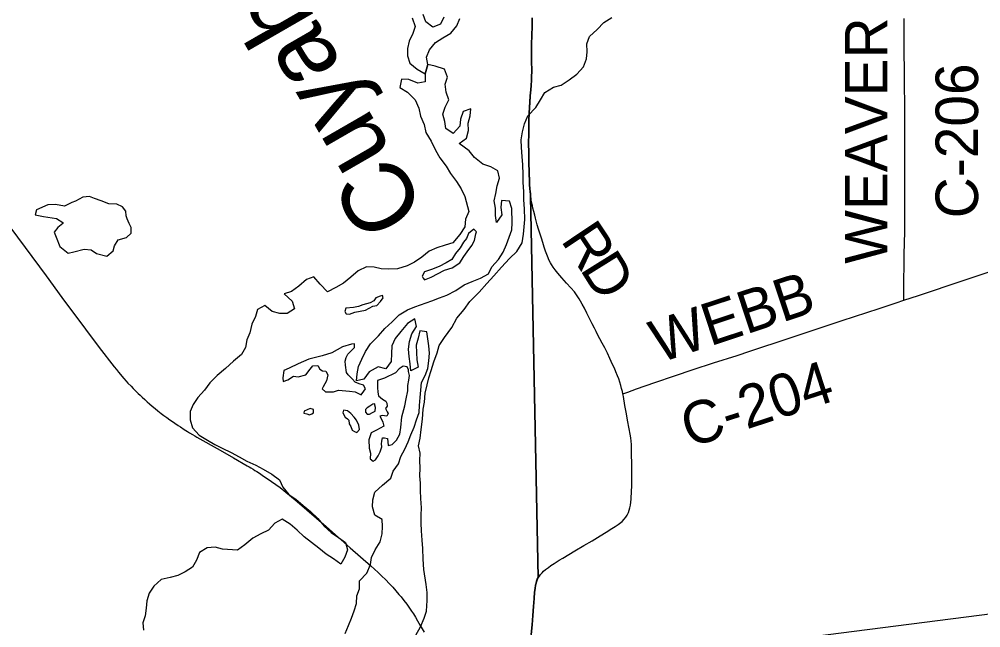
# Model space of a CAD drawing. Extents: x 0 to 34, y 0 to 22.
# Drawn here: x 4.358 to 5.643, y 17.616 to 18.429 of the extents above; entities that cross this region are included whole.
import ezdxf

# ---------------------------------------------------------------- set-up
doc = ezdxf.new("R2010")
doc.units = 0
for name, color, linetype in [('GM_X_Corporation', 7, 'Continuous'), ('GM_X_County_Road', 7, 'Continuous'), ('GM_X_County_Road_Text', 7, 'Continuous'), ('GM_X_Major_Lake', 7, 'Continuous'), ('GM_X_Major_River', 7, 'Continuous'), ('GM_X_Major_River_Text', 7, 'Continuous'), ('GM_X_Minor_Lake', 7, 'Continuous'), ('GM_X_Minor_River', 7, 'Continuous'), ('GM_X_State_Route', 7, 'Continuous'), ('GM_X_Township_Road', 7, 'Continuous'), ('GM_X_Township_Road_Text', 7, 'Continuous'), ('SH_Text', 7, 'Continuous')]:
    doc.layers.add(name, color=color, linetype=linetype)

msp = doc.modelspace()

# ---------------------------------------------------------------- linework, layer by layer
at = {"layer": 'GM_X_Corporation'}
for points in [[(5.0422, 17.6065), (5.0432, 17.6198), (5.0441, 17.6321), (5.0451, 17.6441), (5.046, 17.6549), (5.0467, 17.6631), (5.0472, 17.6682), (5.0479, 17.6725), (5.0486, 17.6754), (5.0493, 17.6779), (5.0502, 17.6805), (5.0513, 17.683), (5.0413, 18.1922), (5.041, 18.1954), (5.0406, 18.1989), (5.0404, 18.2021), (5.04, 18.208), (5.0398, 18.2139), (5.0394, 18.2224), (5.0392, 18.2271), (5.0391, 18.2349), (5.0389, 18.2412), (5.0388, 18.2477), (5.0388, 18.2536), (5.0387, 18.2601), (5.0387, 18.2653), (5.0388, 18.2734), (5.0388, 18.2852), (5.039, 18.2939), (5.0394, 18.3029), (5.0399, 18.3112), (5.0404, 18.3184), (5.0409, 18.3266), (5.0416, 18.3344), (5.042, 18.3404), (5.0424, 18.3475), (5.0427, 18.3534), (5.0428, 18.3582), (5.0428, 18.364), (5.0427, 18.3692), (5.0425, 18.3748), (5.0424, 18.3787), (5.0424, 18.3848), (5.0424, 18.3885), (5.0425, 18.3967), (5.0429, 18.4064), (5.0433, 18.4204), (5.0435, 18.4306)], [(5.0422, 17.6065), (5.0432, 17.6198), (5.0441, 17.6321), (5.0451, 17.6441), (5.046, 17.6549), (5.0467, 17.6631), (5.0472, 17.6682), (5.0479, 17.6725), (5.0486, 17.6754), (5.0493, 17.6779), (5.0502, 17.6805), (5.0513, 17.683), (5.0413, 18.1922), (5.041, 18.1954), (5.0406, 18.1989), (5.0404, 18.2021), (5.04, 18.208), (5.0398, 18.2139), (5.0394, 18.2224), (5.0392, 18.2271), (5.0391, 18.2349), (5.0389, 18.2412), (5.0388, 18.2477), (5.0388, 18.2536), (5.0387, 18.2601), (5.0387, 18.2653), (5.0388, 18.2734), (5.0388, 18.2852), (5.039, 18.2939), (5.0394, 18.3029), (5.0399, 18.3112), (5.0404, 18.3184), (5.0409, 18.3266), (5.0416, 18.3344), (5.042, 18.3404), (5.0424, 18.3475), (5.0427, 18.3534), (5.0428, 18.3582), (5.0428, 18.364), (5.0427, 18.3692), (5.0425, 18.3748), (5.0424, 18.3787), (5.0424, 18.3848), (5.0424, 18.3885), (5.0425, 18.3967), (5.0429, 18.4064), (5.0433, 18.4204), (5.0435, 18.4306)], [(5.0435, 18.4306), (5.0433, 18.4204), (5.0429, 18.4064), (5.0425, 18.3967), (5.0424, 18.3885), (5.0424, 18.3848), (5.0424, 18.3787), (5.0425, 18.3748), (5.0427, 18.3692), (5.0428, 18.364), (5.0428, 18.3582), (5.0427, 18.3534), (5.0424, 18.3475), (5.042, 18.3404), (5.0416, 18.3344), (5.0409, 18.3266), (5.0404, 18.3184), (5.0399, 18.3112), (5.0394, 18.3029), (5.039, 18.2939), (5.0388, 18.2852), (5.0388, 18.2734), (5.0387, 18.2653), (5.0387, 18.2601), (5.0388, 18.2536), (5.0388, 18.2477), (5.0389, 18.2412), (5.0391, 18.2349), (5.0392, 18.2271), (5.0394, 18.2224), (5.0398, 18.2139), (5.04, 18.208), (5.0404, 18.2021), (5.0406, 18.1989), (5.041, 18.1954), (5.0413, 18.1922), (5.0513, 17.683), (5.0502, 17.6805), (5.0493, 17.6779), (5.0486, 17.6754), (5.0479, 17.6725), (5.0472, 17.6682), (5.0467, 17.6631), (5.046, 17.6549), (5.0451, 17.6441), (5.0441, 17.6321), (5.0432, 17.6198), (5.0422, 17.6065)]]:
    msp.add_lwpolyline(points, dxfattribs=at)
at = {"layer": 'GM_X_County_Road'}
for points in [[(5.5403, 18.0535), (5.5404, 18.0653), (5.5408, 18.1144), (5.5414, 18.1454), (5.5415, 18.169), (5.5416, 18.2026), (5.5417, 18.2162), (5.5417, 18.2591), (5.5418, 18.2852), (5.5416, 18.307), (5.5413, 18.3486), (5.5412, 18.3586), (5.5408, 18.3865), (5.5406, 18.402), (5.5406, 18.4299)], [(5.5403, 18.0535), (5.5599, 18.0598), (5.6195, 18.0797), (5.653, 18.0911)], [(5.1646, 17.9281), (5.1711, 17.9306), (5.1831, 17.9351), (5.2075, 17.9434), (5.2337, 17.9522), (5.2588, 17.9607), (5.286, 17.9695), (5.3174, 17.9796), (5.3344, 17.9855), (5.387, 18.0026), (5.4123, 18.0112), (5.4578, 18.0263), (5.5075, 18.0423), (5.5298, 18.0501), (5.5403, 18.0535)]]:
    msp.add_lwpolyline(points, dxfattribs=at)
at = {"layer": 'GM_X_Major_Lake'}
for p, q in [((4.9041, 18.3683), (4.9002, 18.356)), ((4.9041, 18.3683), (4.9002, 18.356)), ((4.9473, 18.1235), (4.941, 18.1159)), ((4.8269, 18.0501), (4.817, 18.0474)), ((4.8609, 17.9563), (4.8462, 17.9494)), ((4.7846, 17.933), (4.799, 17.9319)), ((4.8264, 17.9117), (4.823, 17.9097)), ((4.7459, 17.9004), (4.7489, 17.9016)), ((4.7982, 17.8929), (4.7986, 17.8883))]:
    msp.add_line(p, q, dxfattribs=at)
for points in [[(4.9592, 18.2532), (4.9458, 18.2628), (4.9556, 18.2698), (4.9581, 18.28), (4.958, 18.2899), (4.9605, 18.2998), (4.9612, 18.3093), (4.951, 18.3054), (4.9477, 18.2955), (4.9467, 18.286), (4.9377, 18.2764), (4.9278, 18.2827), (4.9265, 18.2922), (4.9242, 18.302), (4.9271, 18.3116), (4.9319, 18.3211), (4.9284, 18.3313), (4.9271, 18.342), (4.9304, 18.3515), (4.9261, 18.3621), (4.9136, 18.3661), (4.9041, 18.3683)], [(4.9002, 18.356), (4.9003, 18.3454), (4.8904, 18.3434), (4.8787, 18.3483), (4.8688, 18.3486), (4.8666, 18.3379), (4.8769, 18.3316), (4.8868, 18.321), (4.8918, 18.31), (4.8942, 18.2994), (4.8992, 18.2881)], [(4.8992, 18.2881), (4.9012, 18.2775), (4.9084, 18.2658), (4.9142, 18.2541), (4.92, 18.2435), (4.9284, 18.2326), (4.9341, 18.2228), (4.9422, 18.2122), (4.9483, 18.2024), (4.9533, 18.1918), (4.9588, 18.1721), (4.9543, 18.1615), (4.9532, 18.1516), (4.9465, 18.1413), (4.9375, 18.1299), (4.9273, 18.1271), (4.916, 18.1236), (4.9058, 18.119), (4.896, 18.111), (4.8862, 18.1044), (4.8764, 18.0994), (4.8636, 18.0955), (4.8519, 18.0951), (4.8416, 18.0954), (4.8322, 18.0976), (4.8219, 18.0979), (4.8106, 18.0925), (4.8009, 18.084), (4.7911, 18.076), (4.7809, 18.0702), (4.77, 18.0648), (4.7601, 18.075), (4.7517, 18.0848), (4.7418, 18.0813), (4.7317, 18.0721), (4.7219, 18.0652), (4.7121, 18.0621), (4.7224, 18.0523), (4.7255, 18.0417), (4.7157, 18.0356), (4.7059, 18.0355), (4.696, 18.0385), (4.6861, 18.0464), (4.6763, 18.041), (4.6734, 18.0315), (4.6685, 18.0216), (4.666, 18.0098), (4.6619, 18.0003), (4.66, 17.9904), (4.6548, 17.9809), (4.6443, 17.9721), (4.6334, 17.9621), (4.6225, 17.9529), (4.6127, 17.943), (4.6056, 17.9331), (4.5966, 17.9235), (4.5902, 17.914), (4.5862, 17.9045), (4.5862, 17.8935), (4.5893, 17.8829), (4.5981, 17.8731), (4.6092, 17.8664), (4.6194, 17.8604), (4.6289, 17.8555), (4.6411, 17.8499), (4.6517, 17.8443), (4.662, 17.8383), (4.6741, 17.8331), (4.6836, 17.8275), (4.6954, 17.8211), (4.7057, 17.8133), (4.7103, 17.8034), (4.718, 17.7936), (4.7275, 17.7876), (4.7374, 17.779), (4.7473, 17.7711), (4.7568, 17.7617), (4.7652, 17.7515), (4.7747, 17.7429), (4.7843, 17.7365), (4.7938, 17.7297), (4.7965, 17.7199), (4.7928, 17.71), (4.7876, 17.7005), (4.7777, 17.708), (4.7682, 17.714), (4.7583, 17.7219), (4.7484, 17.7294), (4.7388, 17.7373), (4.7293, 17.7459), (4.7198, 17.7542), (4.7091, 17.7606), (4.6993, 17.7556), (4.6911, 17.746), (4.6805, 17.7414), (4.67, 17.7352), (4.6591, 17.7264), (4.6493, 17.7195), (4.6296, 17.7209), (4.6197, 17.7235), (4.6088, 17.7226)], [(4.8223, 17.6887), (4.8271, 17.7002), (4.8285, 17.7097), (4.8337, 17.7196), (4.84, 17.7303), (4.8429, 17.7414), (4.8435, 17.7509), (4.8427, 17.7604), (4.8331, 17.7663), (4.83, 17.7773), (4.8306, 17.7868), (4.8332, 17.7971), (4.8433, 17.8063), (4.8545, 17.8156), (4.8578, 17.8251), (4.8646, 17.8347), (4.8679, 17.8446), (4.873, 17.8545), (4.8775, 17.8641), (4.8812, 17.8736), (4.8856, 17.8839), (4.8889, 17.8934), (4.8922, 17.9033), (4.8928, 17.9128), (4.8939, 17.9235), (4.8945, 17.9334), (4.8955, 17.9433), (4.9003, 17.9528), (4.904, 17.9623), (4.9054, 17.9726), (4.9061, 17.9825), (4.9052, 17.9924), (4.9027, 18.0113), (4.8932, 18.0123), (4.8911, 18.0028), (4.8885, 17.9933), (4.889, 17.9834), (4.8891, 17.9739), (4.8911, 17.9641), (4.881, 17.959), (4.8801, 17.9685), (4.8789, 17.978), (4.878, 17.9879), (4.8794, 17.9981), (4.8827, 18.0084), (4.8886, 18.0184), (4.8866, 18.0286), (4.8768, 18.0224), (4.8679, 18.0117), (4.8604, 18.0021), (4.8556, 17.9925), (4.8553, 17.9823), (4.8551, 17.9716), (4.8476, 17.9617), (4.8377, 17.9642), (4.8257, 17.9576), (4.8182, 17.9477), (4.8084, 17.9456), (4.8094, 17.9552), (4.8112, 17.9647), (4.8156, 17.9746), (4.8205, 17.9849), (4.8272, 17.9949), (4.838, 18.0056), (4.8466, 18.0156), (4.8564, 18.0244), (4.8654, 18.034), (4.8766, 18.0406), (4.8864, 18.0445), (4.9091, 18.0524), (4.9196, 18.0567), (4.9294, 18.0602), (4.9415, 18.0665), (4.9524, 18.0738), (4.9633, 18.0785), (4.9743, 18.0828), (4.9852, 18.0886), (4.9896, 18.0982), (4.9982, 18.1078), (5.0045, 18.1177), (5.009, 18.128), (5.0126, 18.1375), (5.0163, 18.1475), (5.0166, 18.157), (5.0164, 18.1759), (5.0132, 18.1858), (5.0026, 18.1868), (5.0016, 18.1773), (5.0028, 18.1674), (4.9958, 18.1571), (4.9945, 18.1666), (4.9944, 18.1764), (4.9928, 18.1863), (4.995, 18.1958), (4.9967, 18.2061), (4.9996, 18.2164), (4.9976, 18.2262), (4.9881, 18.2318), (4.9775, 18.2351), (4.9664, 18.2441), (4.9592, 18.2532)], [(4.941, 18.1159), (4.9358, 18.1078), (4.9286, 18.1032), (4.9192, 18.0986), (4.909, 18.0944), (4.8996, 18.0913), (4.8962, 18.0855), (4.8978, 18.0829), (4.8997, 18.0806), (4.9083, 18.0841), (4.9261, 18.0934), (4.9366, 18.0965), (4.9468, 18.1034), (4.952, 18.1118), (4.9565, 18.1179), (4.9629, 18.1266), (4.9662, 18.1331), (4.9681, 18.1422), (4.9692, 18.1449), (4.9654, 18.1483), (4.9582, 18.1425), (4.9556, 18.1361), (4.9515, 18.1311), (4.9473, 18.1235)], [(4.817, 18.0474), (4.8114, 18.0451), (4.8046, 18.0435), (4.7944, 18.0427), (4.7929, 18.0385), (4.7948, 18.0354), (4.799, 18.0347), (4.8065, 18.0374), (4.8205, 18.0402), (4.8303, 18.0456), (4.8356, 18.0464), (4.8405, 18.0517), (4.8442, 18.0567), (4.8434, 18.0597), (4.84, 18.0589), (4.8344, 18.0566), (4.8318, 18.0524), (4.8269, 18.0501)], [(4.799, 17.9319), (4.807, 17.9309), (4.8146, 17.9271), (4.8183, 17.9317), (4.8206, 17.9351), (4.8179, 17.9397), (4.8122, 17.9415), (4.8069, 17.9438), (4.8027, 17.9483), (4.7973, 17.9535), (4.7954, 17.9569), (4.7938, 17.9664), (4.7934, 17.9721), (4.7949, 17.977), (4.7971, 17.9812), (4.8024, 17.9866), (4.8061, 17.9904), (4.8061, 17.9953), (4.8019, 17.9945), (4.7898, 17.991), (4.7755, 17.9833), (4.7627, 17.9791), (4.7449, 17.9744), (4.7306, 17.9686), (4.7185, 17.9628), (4.7114, 17.9593), (4.7099, 17.9498), (4.7107, 17.9449), (4.7168, 17.9469), (4.7243, 17.9518), (4.7304, 17.9511), (4.7409, 17.9539), (4.7466, 17.9611), (4.7503, 17.9657), (4.7567, 17.9661), (4.7594, 17.9612), (4.7632, 17.959), (4.7674, 17.9586), (4.7701, 17.9537), (4.7683, 17.9457), (4.7638, 17.9377), (4.7627, 17.9351), (4.7672, 17.9309), (4.7778, 17.931), (4.7846, 17.933)], [(4.8462, 17.9494), (4.8367, 17.9459), (4.8368, 17.9417), (4.8368, 17.9368), (4.8372, 17.9303), (4.838, 17.9258), (4.8434, 17.9213), (4.8476, 17.9187), (4.8491, 17.9156), (4.8495, 17.9118), (4.8473, 17.9088), (4.8496, 17.9043), (4.8511, 17.902), (4.8492, 17.8986), (4.8428, 17.8993), (4.8398, 17.8985), (4.8413, 17.8962), (4.844, 17.8906), (4.8452, 17.8853), (4.8354, 17.8799), (4.8282, 17.876), (4.8249, 17.8669), (4.8253, 17.8555), (4.8273, 17.8491), (4.827, 17.8415), (4.8308, 17.8381), (4.8338, 17.84), (4.8375, 17.8454), (4.8401, 17.8507), (4.8424, 17.8576), (4.8419, 17.8613), (4.8423, 17.8651), (4.8434, 17.8697), (4.846, 17.8697), (4.8502, 17.8686), (4.851, 17.8591), (4.8563, 17.8607), (4.862, 17.8664), (4.8664, 17.8744), (4.8679, 17.8832), (4.8693, 17.8976), (4.873, 17.9124), (4.8748, 17.9215), (4.877, 17.9325), (4.8773, 17.9394), (4.8784, 17.9466), (4.8795, 17.953), (4.8783, 17.958), (4.8779, 17.9602), (4.8763, 17.9644), (4.871, 17.9651), (4.8658, 17.9617), (4.8609, 17.9563)], [(4.7489, 17.9016), (4.7512, 17.9027), (4.7511, 17.9073), (4.7466, 17.9088), (4.7387, 17.9053), (4.7383, 17.9026), (4.7421, 17.9015), (4.7459, 17.9004)], [(4.7986, 17.8883), (4.8009, 17.8845), (4.8028, 17.8796), (4.8059, 17.8778), (4.8089, 17.8766), (4.8127, 17.8805), (4.8119, 17.8865), (4.8088, 17.8933), (4.8053, 17.8971), (4.8011, 17.902), (4.7966, 17.9054), (4.7913, 17.9065), (4.7905, 17.9031), (4.7936, 17.897), (4.7967, 17.8948), (4.7982, 17.8929)], [(4.823, 17.9097), (4.8208, 17.9075), (4.8204, 17.904), (4.8227, 17.901), (4.8261, 17.901), (4.8299, 17.9034), (4.8337, 17.9053), (4.834, 17.9102), (4.8332, 17.9132), (4.8332, 17.9151), (4.8302, 17.9147), (4.8264, 17.9117)], [(4.6088, 17.7226), (4.5986, 17.7161), (4.5949, 17.7062), (4.5893, 17.6967), (4.5795, 17.6905), (4.5697, 17.6855), (4.5595, 17.6828), (4.5474, 17.6801), (4.5376, 17.6713), (4.5316, 17.6617), (4.5283, 17.6518), (4.5273, 17.642), (4.5262, 17.6317), (4.5229, 17.6222), (4.5237, 17.6124)], [(4.7936, 17.608), (4.798, 17.6187), (4.8017, 17.6285), (4.8055, 17.6381), (4.8088, 17.6483), (4.8091, 17.6582), (4.8124, 17.6677), (4.8127, 17.6783), (4.8223, 17.6887)]]:
    msp.add_lwpolyline(points, dxfattribs=at)
at = {"layer": 'GM_X_Major_River'}
msp.add_line((4.9002, 18.356), (4.9041, 18.3683), dxfattribs=at)
msp.add_line((4.9002, 18.356), (4.9041, 18.3683), dxfattribs=at)
for points in [[(4.9253, 18.4317), (4.9209, 18.4222), (4.9107, 18.4183), (4.9012, 18.4254), (4.8977, 18.4353)], [(4.883, 18.431), (4.8872, 18.4192), (4.8839, 18.4097), (4.879, 18.3995), (4.8768, 18.39), (4.8769, 18.3801), (4.88, 18.3703), (4.8895, 18.3624), (4.9002, 18.356)], [(4.9041, 18.3683), (4.9021, 18.3781), (4.9062, 18.388), (4.9144, 18.3976), (4.9242, 18.4042), (4.9347, 18.4104), (4.9429, 18.42), (4.9466, 18.4299)]]:
    msp.add_lwpolyline(points, dxfattribs=at)
at = {"layer": 'GM_X_Minor_Lake'}
msp.add_line((4.4777, 18.182), (4.4674, 18.1861), dxfattribs=at)
msp.add_lwpolyline([(4.4674, 18.1861), (4.4583, 18.1895), (4.4515, 18.1921), (4.4428, 18.1913), (4.433, 18.1859), (4.4281, 18.1839), (4.4183, 18.1793), (4.4061, 18.1811), (4.3959, 18.1807), (4.3808, 18.1741), (4.379, 18.1676), (4.39, 18.1654), (4.4074, 18.1625), (4.4158, 18.1573), (4.4158, 18.1558), (4.4094, 18.1508), (4.4045, 18.1443), (4.4072, 18.1375), (4.4119, 18.1254), (4.4233, 18.1164), (4.4308, 18.118), (4.4444, 18.1215), (4.4539, 18.1208), (4.4611, 18.1159), (4.4748, 18.1122), (4.4831, 18.1195), (4.4849, 18.1263), (4.4901, 18.134), (4.5011, 18.1371), (4.5075, 18.1428), (4.5074, 18.1504), (4.5047, 18.1561), (4.502, 18.1621), (4.5005, 18.1663), (4.5001, 18.1724), (4.4959, 18.1784), (4.4883, 18.1817), (4.4777, 18.182)], dxfattribs=at)
at = {"layer": 'GM_X_Minor_River'}
for points in [[(5.0302, 18.1302), (5.032, 18.1416), (5.0334, 18.1613), (5.0333, 18.1757), (5.0324, 18.1875), (5.0323, 18.1981), (5.0315, 18.211), (5.0314, 18.2212), (5.0309, 18.2345), (5.0301, 18.2455), (5.0292, 18.2576), (5.0288, 18.2679), (5.0306, 18.2785), (5.0332, 18.2891), (5.0376, 18.2998), (5.0485, 18.3109), (5.0545, 18.3212), (5.0605, 18.3311), (5.0718, 18.338), (5.082, 18.3407), (5.0929, 18.348), (5.103, 18.3553), (5.112, 18.3652), (5.1161, 18.3759), (5.1168, 18.3854), (5.1167, 18.396), (5.1201, 18.4059), (5.1302, 18.4151), (5.1392, 18.4246), (5.1498, 18.4311)], [(4.8878, 17.6057), (4.8942, 17.6167), (4.899, 17.6285), (4.9023, 17.638), (4.903, 17.6521), (4.9029, 17.6627), (4.9017, 17.6737), (4.8985, 17.6934), (4.8976, 17.7074), (4.8972, 17.7218), (4.8963, 17.7328), (4.8955, 17.7453), (4.895, 17.7556), (4.8949, 17.7662), (4.8956, 17.776), (4.8947, 17.7882), (4.8943, 17.7992), (4.8942, 17.8087), (4.8934, 17.8185), (4.8937, 17.8288), (4.8932, 17.8394), (4.8939, 17.8489), (4.8915, 17.8587), (4.8937, 17.869), (4.8952, 17.8807), (4.8969, 17.8944), (4.8976, 17.9077), (4.8994, 17.9172), (4.9005, 17.9293), (4.903, 17.9403), (4.9052, 17.9498), (4.9082, 17.9593), (4.9119, 17.9711), (4.9163, 17.9833), (4.9189, 17.9928), (4.9264, 18.0038), (4.9361, 18.0168), (4.9425, 18.0294), (4.9526, 18.0408), (4.9601, 18.0515), (4.9725, 18.0641), (4.9826, 18.0756), (4.992, 18.0859), (5.0025, 18.0977), (5.013, 18.1092), (5.0231, 18.1184), (5.0302, 18.1302)]]:
    msp.add_lwpolyline(points, dxfattribs=at)
at = {"layer": 'GM_X_State_Route'}
msp.add_lwpolyline([(4.3467, 18.1497), (4.3936, 18.0862), (4.4147, 18.057), (4.4463, 18.0147), (4.4644, 17.9902), (4.4846, 17.9642), (4.4876, 17.9606), (4.4902, 17.9574), (4.4929, 17.9541), (4.495, 17.9517), (4.4975, 17.9489), (4.5007, 17.9453), (4.5031, 17.9427), (4.5072, 17.9385), (4.5101, 17.9354), (4.5123, 17.9332), (4.5168, 17.9288), (4.5193, 17.9263), (4.5221, 17.9238), (4.5256, 17.9205), (4.5289, 17.9175), (4.5317, 17.9151), (4.5356, 17.9118), (4.5393, 17.9086), (4.543, 17.9056), (4.5475, 17.9021), (4.5511, 17.8994), (4.5549, 17.8966), (4.559, 17.8936), (4.5624, 17.8913), (4.5659, 17.8889), (4.5703, 17.8859), (4.5731, 17.8841), (4.5783, 17.8808), (4.5828, 17.8779), (4.5855, 17.8763), (4.5892, 17.8741), (4.5926, 17.8721), (4.5951, 17.8706), (4.6264, 17.8528), (4.6443, 17.8428), (4.6626, 17.832), (4.6649, 17.8307), (4.6674, 17.8292), (4.6704, 17.8274), (4.6727, 17.8259), (4.6752, 17.8243), (4.6801, 17.8212), (4.6829, 17.8193), (4.688, 17.8159), (4.6951, 17.8112), (4.7067, 17.8029), (4.7141, 17.7971), (4.7293, 17.7843), (4.7681, 17.7511), (4.8002, 17.7227), (4.8278, 17.6985), (4.8374, 17.6896), (4.842, 17.6851), (4.8476, 17.6796), (4.8521, 17.6748), (4.8571, 17.6697), (4.861, 17.6652), (4.8653, 17.6603), (4.8681, 17.6569), (4.872, 17.6521), (4.8758, 17.647), (4.8787, 17.6431), (4.8822, 17.6379), (4.8846, 17.6343), (4.8875, 17.6297), (4.8903, 17.6249), (4.8938, 17.6187), (4.899, 17.6099)], dxfattribs=at)
at = {"layer": 'GM_X_Township_Road'}
for points in [[(5.0415, 18.1916), (5.0412, 18.1948), (5.0409, 18.1984), (5.0406, 18.2016), (5.0402, 18.2074), (5.04, 18.2134), (5.0396, 18.2219), (5.0394, 18.2265), (5.0393, 18.2343), (5.0392, 18.2407), (5.0391, 18.2472), (5.039, 18.2531), (5.0389, 18.2596), (5.0389, 18.2647), (5.039, 18.2728), (5.039, 18.2847), (5.0392, 18.2933), (5.0396, 18.3023), (5.0401, 18.3107), (5.0406, 18.3178), (5.0411, 18.3261), (5.0418, 18.3338), (5.0422, 18.3399), (5.0426, 18.347), (5.0429, 18.3529), (5.043, 18.3577), (5.043, 18.3635), (5.0429, 18.3686), (5.0427, 18.3743), (5.0426, 18.3781), (5.0426, 18.3842), (5.0426, 18.388), (5.0427, 18.3961), (5.0431, 18.4059), (5.0435, 18.4198), (5.0437, 18.4301)], [(5.1646, 17.9281), (5.164, 17.9314), (5.163, 17.9355), (5.162, 17.9394), (5.1606, 17.9438), (5.1592, 17.9482), (5.1576, 17.9524), (5.1553, 17.9579), (5.1533, 17.9625), (5.1509, 17.9677), (5.1474, 17.9754), (5.144, 17.9826), (5.1422, 17.9863), (5.1404, 17.9899), (5.1371, 17.9961), (5.134, 18.0018), (5.1317, 18.006), (5.1288, 18.0118), (5.1267, 18.016), (5.1238, 18.022), (5.1201, 18.0291), (5.1164, 18.0363), (5.1132, 18.0426), (5.1104, 18.048), (5.1082, 18.0521), (5.1061, 18.0554), (5.1026, 18.0606), (5.0998, 18.0645), (5.0949, 18.07), (5.0891, 18.0764), (5.0831, 18.0831), (5.0777, 18.0895), (5.074, 18.0938), (5.0713, 18.0975), (5.0691, 18.1011), (5.0678, 18.1034), (5.0658, 18.1074), (5.0646, 18.1101), (5.0628, 18.1146), (5.0613, 18.1189), (5.0595, 18.1244), (5.0577, 18.1304), (5.0558, 18.1364), (5.0536, 18.143), (5.0519, 18.1485), (5.0503, 18.1541), (5.0489, 18.1595), (5.0478, 18.1632), (5.0468, 18.1672), (5.0457, 18.1718), (5.0445, 18.1762), (5.0437, 18.1798), (5.0427, 18.1843), (5.0422, 18.1874), (5.0419, 18.1895), (5.0415, 18.1916)], [(5.0515, 17.6824), (5.0531, 17.6846), (5.0546, 17.6867), (5.0566, 17.6889), (5.0587, 17.6912), (5.0614, 17.6936), (5.0652, 17.6963), (5.0683, 17.6987), (5.0726, 17.7015), (5.0793, 17.7058), (5.0843, 17.7088), (5.1003, 17.7183), (5.1124, 17.7254), (5.1234, 17.732), (5.1341, 17.7384), (5.1422, 17.7433), (5.1501, 17.7481), (5.1545, 17.7511), (5.1582, 17.7536), (5.1636, 17.7578), (5.1664, 17.7607), (5.1686, 17.7635), (5.1703, 17.7661), (5.172, 17.7698), (5.1731, 17.7727), (5.174, 17.7759), (5.1747, 17.7794), (5.1753, 17.7834), (5.1757, 17.7874), (5.1763, 17.7985), (5.1765, 17.8044), (5.1765, 17.8174), (5.1765, 17.8345), (5.1764, 17.8482), (5.1764, 17.8563), (5.1763, 17.8604), (5.1759, 17.8652), (5.1753, 17.8695), (5.1744, 17.8742), (5.173, 17.8816), (5.1709, 17.893), (5.1694, 17.9014), (5.1674, 17.9127), (5.1653, 17.9246), (5.1646, 17.9281)], [(5.0424, 17.606), (5.0434, 17.6192), (5.0443, 17.6315), (5.0453, 17.6436), (5.0462, 17.6544), (5.0469, 17.6625), (5.0474, 17.6676), (5.0481, 17.6719), (5.0488, 17.6749), (5.0495, 17.6774), (5.0504, 17.68), (5.0515, 17.6824)]]:
    msp.add_lwpolyline(points, dxfattribs=at)
at = {"layer": 'SH_Text'}
msp.add_lwpolyline([(9.4006, 18.113), (4.9378, 17.5422), (9.4006, 17.763)], close=True, dxfattribs=at)

# ---------------------------------------------------------------- texts
at = {"layer": 'GM_X_County_Road_Text'}
for s, rotation, p in [('WEAVER', 90, (5.5184, 18.1021)), ('C-206', 90, (5.6395, 18.1629)), ('WEBB', 18.2856, (5.213, 17.9691)), ('C-204', 18.0885, (5.2537, 17.8557))]:
    msp.add_text(s, height=0.05682, rotation=rotation, dxfattribs=at).set_placement(p)
at = {"layer": 'GM_X_Major_River_Text'}
msp.add_text('Cuyahoga', height=0.09474, rotation=119.9689, dxfattribs=at).set_placement((4.9026, 18.1729))
at = {"layer": 'GM_X_Township_Road_Text'}
for s, rotation, p in [('R', 303.7702, (5.0807, 18.1336)), ('D', 301.9359, (5.1064, 18.0952))]:
    msp.add_text(s, height=0.0568, rotation=rotation, dxfattribs=at).set_placement(p)

doc.saveas('drawing.dxf')
